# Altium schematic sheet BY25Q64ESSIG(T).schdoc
size 127 x 101 mm
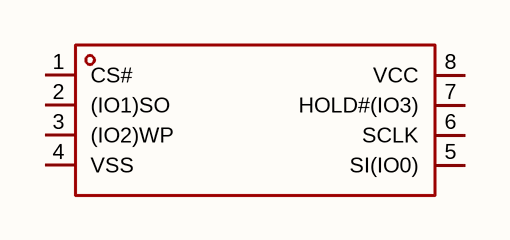
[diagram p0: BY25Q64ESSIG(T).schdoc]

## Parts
U?  by25q64essig(t)  [SOIC-8_L5.3-W5.3-P1.27-LS7.9-BL]  (value not drawn)

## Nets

Not connected (* = marked no-connect by the designer): U? 1(CS#) 2((IO1)SO) 3((IO2)WP) 4(VSS) 5(SI(IO0)) 6(SCLK) 7(HOLD#(IO3)) 8(VCC)

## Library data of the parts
U? = by25q64essig(t): 是 64M 位串行外设接口 (SPI) 闪存，支持双/四 SPI：串行时钟、片选、串行数据 I/O0 (SI)、I/O1 (SO)、I/O2 (/WP) 和 I/O3 (/HOLD)。双 I/O 数据传输速度为 100Mbits/s，四 I/O 和四输出数据传输速度为 200Mbits/s。该器件使用单一低电压电源，范围为 2.7V 至 3.6V。此外，该器件支持 JEDEC 标准制造商和设备 ID 以及三个 1024 字节安全寄存器。; Manufacturer: BOYAMICRO(博雅); AddInBom: yes; ModelId: 78e311bc6cdb4f2a8ea91f8efea56c7d; ModelTransform: 311.023,207.8736,0,90,0,0,0,0,0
